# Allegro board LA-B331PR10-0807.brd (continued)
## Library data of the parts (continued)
U5 U51 U54 U60 U61 UH1 = SN74AHC1G08DCKR_SC70-5
U6 = APL3512ABI-TRG_SOT23-5
U7 = SN74AHC1G04DCKR_SOT23-5
U21 = AT97SC3205_TSSOP28
U24 U34 U57 U59 = APE8937GN2_DFN8_2X2
U25-U27 U29 U30 U33 = TPS22966DPUR_SON14_2X3
U28 = NCP4545IMNTWG_QFN18_3X3
U37 UC1 = 74AUP1G07GW_TSSOP5
U38 = MEC1641-PZV_TFBGA_144P
U46 = APX9136QFI-TRG_VTDFN6_1P6X1P6
U53 = TXB0104YZTR_DSBGA_12P
U56 = PS8713BTQFN24GTR2_TQFN24_4X4
U58 = G601A31U_ADFN6_1P5X1P5
UCPU1 = BDW-Y-LPDDR3_BGA_1234P-T
UD1-UD8 = MT41J256M16RE-15E-D_FBGA_96P
Y3 = Y_9H03200031_2P
YH1 = Y_9H03220008_2P
YH2 = Y_X3G024000DC1H_4P

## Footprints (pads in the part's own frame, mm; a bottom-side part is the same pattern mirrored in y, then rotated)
74AUP1G07GW_TSSOP5
  oval 0.381x1.346 smd: 1(0,0) 2(0.65,0) 3(1.3,0) 4(1.3,1.79) 5(0,1.79)
74CBTLV3126DS_SSOP16
  oval 0.381x1.676 smd: 1(0,0) 2(0.635,0) 3(1.27,0) 4(1.905,0) 5(2.54,0) 6(3.175,0) 7(3.81,0) 8(4.445,0) 9(4.445,5.35) 10(3.81,5.35) 11(3.175,5.35) 12(2.54,5.35) 13(1.905,5.35) 14(1.27,5.35) 15(0.635,5.35) 16(0,5.35)
ACES_50278-00201-001_2P
  oval 0.787x1.905 smd: 1(0,0) 2(1.25,0)
  rect 1.295x3.353 smd: 3(-2.85,-4.925) 4(4.1,-4.925)
ACES_50281-00601-001_6P-T
  oval 0.787x2.007 smd: 1(0,0) 2(1.25,0) 3(2.5,0) 4(3.75,0) 5(5,0) 6(6.25,0)
  rect 2.007x2.489 smd: 7(-2.2,-4.05) 8(8.45,-4.05)
ACES_50406-02071-001_20P
  oval 0.254x1.295 smd: 1(0,0) 2(0.5,0) 3(1,0) 4(1.5,0) 5(2,0) 6(2.5,0) 7(3,0) 8(3.5,0) 9(4,0) 10(4.5,0) 11(5,0) 12(5.5,0) 13(6,0) 14(6.5,0) 15(7,0) 16(7.5,0) 17(8,0) 18(8.5,0) 19(9,0) 20(9.5,0)
  rect 1.194x2.692 smd: 21(-2.4,1.95) 22(11.9,1.95)
  rect 2.311x1.295 smd: 23(0.85,3.9) 24(8.65,3.9)
ACES_50406-03071-001_30P
  oval 0.254x1.295 smd: 1(0,0) 2(0.5,0) 3(1,0) 4(1.5,0) 5(2,0) 6(2.5,0) 7(3,0) 8(3.5,0) 9(4,0) 10(4.5,0) 11(5,0) 12(5.5,0) 13(6,0) 14(6.5,0) 15(7,0) 16(7.5,0) 17(8,0) 18(8.5,0) 19(9,0) 20(9.5,0) 21(10,0) 22(10.5,0) 23(11,0) 24(11.5,0) 25(12,0) 26(12.5,0) 27(13,0) 28(13.5,0) 29(14,0) 30(14.5,0)
  rect 1.194x2.692 smd: 31(16.9,1.95) 35(-2.4,1.95)
  rect 2.311x1.295 smd: 32(13.65,3.9) 33(7.25,3.9) 34(0.85,3.9)
ACES_50521-0084N-P01_8P
  oval 0.305x1.092 smd: 1(0,0) 2(-0.5,0) 3(-1,0) 4(-1.5,0) 5(-2,0) 6(-2.5,0) 7(-3,0) 8(-3.5,0)
  rect 0.406x0.787 smd: 9(1,-2.65) 10(-4.5,-2.65)
ACES_50521-01041-P01_10P
  oval 0.305x0.787 smd: 1(0,0) 2(0.5,0) 3(1,0) 4(1.5,0) 5(2,0) 6(2.5,0) 7(3,0) 8(3.5,0) 9(4,0) 10(4.5,0)
  rect 0.406x0.787 smd: 11(-1,-2.5) 12(5.5,-2.5)
ACES_50696-0200M-001_20P-T
  oval 0.305x0.787 smd: 1(0,0) 2(0.5,0) 3(1,0) 4(1.5,0) 5(2,0) 6(2.5,0) 7(3,0) 8(3.5,0) 9(4,0) 10(4.5,0) 11(5,0) 12(5.5,0) 13(6,0) 14(6.5,0) 15(7,0) 16(7.5,0) 17(8,0) 18(8.5,0) 19(9,0) 20(9.5,0)
  rect 0.406x0.787 smd: 21(-1,-2.5) 22(10.5,-2.5)
ACES_51015-05001-002_50P
  oval 0.203x0.762 smd: 1(0,0) 2(0,3.95) 3(0.4,0) 4(0.4,3.95) 5(0.8,0) 6(0.8,3.95) 7(1.2,0) 8(1.2,3.95) 9(1.6,0) 10(1.6,3.95) 11(2,0) 12(2,3.95) 13(2.4,0) 14(2.4,3.95) 15(2.8,0) 16(2.8,3.95) 17(3.2,0) 18(3.2,3.95) 19(3.6,0) 20(3.6,3.95) 21(4,0) 22(4,3.95) 23(4.4,0) 24(4.4,3.95) 25(4.8,0) 26(4.8,3.95) 27(5.2,0) 28(5.2,3.95) 29(5.6,0) 30(5.6,3.95) 31(6,0) 32(6,3.95) 33(6.4,0) 34(6.4,3.95) 35(6.8,0) 36(6.8,3.95) 37(7.2,0) 38(7.2,3.95) 39(7.6,0) 40(7.6,3.95) 41(8,0) 42(8,3.95) 43(8.4,0) 44(8.4,3.95) 45(8.8,0) 46(8.8,3.95) 47(9.2,0) 48(9.2,3.95) 49(9.6,0) 50(9.6,3.95)
  rect 0.559x0.508 smd: 51(-1.115,2.425) 52(-1.115,1.525) 53(10.715,2.425) 54(10.715,1.525)
AON7405_DFN8-5
  oval 0.406x0.991 smd: 1(0,0) 2(0.66,0) 3(1.32,0) 4(1.98,0)
  custom 0.559x0.559 smd: 5(0.99,2.247)
AON7934_DFN3X3A8-10
  oval 0.457x0.508 smd: 1(0,0) 2(0.65,0) 3(1.3,0) 4(1.95,0) 5(1.95,2.76) 6(1.3,2.76) 7(0.65,2.76) 8(0,2.76)
  rect 2.54x1.041 smd: 9(0.975,1.813)
  rect 2.54x0.559 smd: 10(0.975,0.708)
APE8937GN2_DFN8_2X2
  oval 0.254x0.787 smd: 1(0,0) 2(0.5,0) 3(1,0) 4(1.5,0) 5(1.5,2.2) 6(1,2.2) 7(0.5,2.2) 8(0,2.2)
  rect 1.6x0.889 smd: 9(0.75,1.1)
APL3512ABI-TRG_SOT23-5
  oval 0.61x1.041 smd: 1(0,0) 2(0.95,0) 3(1.9,0) 4(1.9,2.7) 5(0,2.7)
APX9136QFI-TRG_VTDFN6_1P6X1P6
  oval 0.254x0.737 smd: 1(0,0) 2(0.5,0) 3(1,0) 4(1,1.86) 5(0.5,1.86) 6(0,1.86)
  rect 0.991x0.61 smd: 7(0.5,0.93)
AT97SC3205_TSSOP28
  oval 0.381x1.626 smd: 1(0,0) 2(0.65,0) 3(1.3,0) 4(1.95,0) 5(2.6,0) 6(3.25,0) 7(3.9,0) 8(4.55,0) 9(5.2,0) 10(5.85,0) 11(6.5,0) 12(7.15,0) 13(7.8,0) 14(8.45,0) 15(8.45,5.8) 16(7.8,5.8) 17(7.15,5.8) 18(6.5,5.8) 19(5.85,5.8) 20(5.2,5.8) 21(4.55,5.8) 22(3.9,5.8) 23(3.25,5.8) 24(2.6,5.8) 25(1.95,5.8) 26(1.3,5.8) 27(0.65,5.8) 28(0,5.8)
BAT54CW-7-F_SOT323-3
  oval 0.711x0.889 smd: 1(0,0) 2(-0.65,-1.9) 3(0.65,-1.9)
BAT54CW_SOT323-3
  oval 0.61x0.559 smd: 1(0,0) 2(-0.65,-1.85) 3(0.65,-1.85)
BAT54HT1G_SOD323-2
  rect 0.635x0.838 smd: 1(0,0) 2(2.225,0)
BDW-Y-LPDDR3_BGA_1234P-T
  round 0.305 smd: A6(-1.25,0) A42(-14.484,0) A44(-14.984,0) C5(-1,0.433) C43(-14.734,0.433) C45(-15.234,0.433) CR45(-15.234,27.435) CU1(0,27.984) CU44(-14.984,27.868) CV3(-0.435,28.234) CV43(-14.734,28.301) CV45(-15.234,28.301) CW1(0,28.484) CW5(-0.868,28.484) CY3(-0.435,28.734) CY7(-1.301,28.734) CY42(-14.484,28.734) CY44(-14.984,28.734) D2(-0.25,0.866) D4(-0.75,0.866) D44(-14.984,0.866) F1(0,1.299) F3(-0.5,1.299) F45(-15.234,1.299) H2(-0.25,1.732) J1(0,2.165)
  round 0.279 smd: A8(-1.75,0) A10(-2.25,0) A14(-3.3,0) A16(-4.166,0) A18(-5.032,0) A20(-5.898,0) A22(-6.764,0) A24(-7.63,0) A26(-8.496,0) A28(-9.362,0) A30(-10.228,0) A32(-11.094,0) A34(-11.96,0) A36(-12.943,0) A38(-13.484,0) A40(-13.984,0) AA1(0,5.629) AA45(-15.234,5.629) AC1(0,6.495) AC45(-15.234,6.495) AE1(0,7.361) AE45(-15.234,7.361) AG1(0,8.227) AG45(-15.234,8.227) AJ1(0,9.093) AJ45(-15.234,9.093) AM1(0,9.959) AM45(-15.234,9.959) AP1(0,10.903) AP45(-15.234,10.903) AT1(0,11.769) AT45(-15.234,11.769) AV1(0,12.635) AV45(-15.234,12.635) AY1(0,13.501) AY45(-15.234,13.501) BB1(0,14.367) BB45(-15.234,14.367) BD1(0,15.233) BD45(-15.234,15.233) BF1(0,16.099) BF45(-15.234,16.099) BH1(0,16.965) BH45(-15.234,16.965) BK1(0,17.831) BK45(-15.234,17.831) BM1(0,18.697) BM45(-15.234,18.697) BP1(0,19.563) BP45(-15.234,19.563) BT1(0,20.429) BT45(-15.234,20.429) BV1(0,21.295) BV45(-15.234,21.295) BY1(0,22.161) BY45(-15.234,22.161) CB1(0,23.027) CB45(-15.234,23.027) CD1(0,23.893) CD45(-15.234,23.893) CF1(0,24.759) CF45(-15.234,24.759) CH1(0,25.703) CH45(-15.234,25.703) CL1(0,26.484) CM45(-15.234,26.569) CN1(0,26.984) CR1(0,27.484) CY10(-2.167,28.734) CY13(-3.033,28.734) CY15(-3.899,28.734) CY17(-4.765,28.734) CY19(-5.631,28.734) CY21(-6.497,28.734) CY23(-7.363,28.734) CY25(-8.229,28.734) CY27(-9.095,28.734) CY29(-9.961,28.734) CY31(-10.827,28.734) CY33(-11.693,28.734) CY36(-12.984,28.734) CY38(-13.484,28.734) CY40(-13.984,28.734) J45(-15.234,2.165) N1(0,3.031) N45(-15.234,3.031) T1(0,3.897) T45(-15.234,3.897) W1(0,4.763) W45(-15.234,4.763)
  round 0.254 smd: AA3(-0.5,5.629) AA5(-1,5.629) AA7(-1.5,5.629) AA9(-2,5.629) AA11(-2.5,5.629) AA13(-3,5.629) AA15(-3.5,5.629) AA17(-4.552,5.549) AA18(-5.107,5.707) AA19(-5.707,5.707) AA21(-6.307,5.707) AA22(-6.859,5.707) AA24(-7.459,5.707) AA25(-8.059,5.707) AA26(-8.611,5.707) AA28(-9.211,5.707) AA29(-9.811,5.707) AA30(-10.363,5.707) AA32(-10.963,5.707) AA33(-11.563,5.707) AA34(-12.115,5.707) AA35(-12.734,5.629) AA37(-13.234,5.629) AA39(-13.734,5.629) AA41(-14.234,5.629) AA43(-14.734,5.629) AB2(-0.25,6.062) AB4(-0.75,6.062) AB6(-1.25,6.062) AB8(-1.75,6.062) AB10(-2.25,6.062) AB12(-2.75,6.062) AB14(-3.25,6.062) AB15(-4.057,6.249) AB16(-4.087,5.749) AB36(-12.984,6.062) AB38(-13.484,6.062) AB40(-13.984,6.062) AB42(-14.484,6.062) AB44(-14.984,6.062) AC3(-0.5,6.495) AC5(-1,6.495) AC7(-1.5,6.495) AC9(-2,6.495) AC11(-2.5,6.495) AC13(-3,6.495) AC15(-3.5,6.495) AC17(-4.555,6.316) AC18(-5.107,6.316) AC19(-5.707,6.316) AC21(-6.307,6.316) AC22(-6.859,6.316) AC24(-7.459,6.316) AC25(-8.059,6.316) AC26(-8.611,6.316) AC28(-9.211,6.316) AC29(-9.811,6.316) AC30(-10.363,6.316) AC32(-10.963,6.316) AC33(-11.563,6.316) AC34(-12.115,6.316) AC35(-12.734,6.495) AC37(-13.234,6.495) AC39(-13.734,6.495) AC41(-14.234,6.495) AC43(-14.734,6.495) AD2(-0.25,6.928) AD4(-0.75,6.928) AD6(-1.25,6.928) AD8(-1.75,6.928) AD10(-2.25,6.928) AD12(-2.75,6.928) AD14(-3.25,6.928) AD16(-4.067,6.77) AD17(-4.555,6.924) AD18(-5.107,6.924) AD19(-5.707,6.924) AD21(-6.307,6.924) AD22(-6.859,6.924) AD24(-7.459,6.924) AD25(-8.059,6.924) AD26(-8.611,6.924) AD28(-9.211,6.924) AD29(-9.811,6.924) AD30(-10.363,6.924) AD32(-10.963,6.924) AD33(-11.563,6.924) AD34(-12.115,6.924) AD36(-12.984,6.928) AD38(-13.484,6.928) AD40(-13.984,6.928) AD42(-14.484,6.928) AD44(-14.984,6.928) AE3(-0.5,7.361) AE5(-1,7.361) AE7(-1.5,7.361) AE9(-2,7.361) AE11(-2.5,7.361) AE13(-3,7.361) AE15(-3.5,7.361) AE16(-4.117,7.286) AE17(-4.555,7.533) AE18(-5.107,7.533) AE19(-5.707,7.533) AE21(-6.307,7.533) AE22(-6.859,7.533) AE24(-7.459,7.533) AE25(-8.059,7.533) AE26(-8.611,7.533) AE28(-9.211,7.533) AE29(-9.811,7.533) AE30(-10.363,7.533) AE32(-10.963,7.533) AE33(-11.563,7.533) AE34(-12.115,7.533) AE35(-12.734,7.361) AE37(-13.234,7.361) AE39(-13.734,7.361) AE41(-14.234,7.361) AE43(-14.734,7.361) AF2(-0.25,7.794) AF4(-0.75,7.794) AF6(-1.25,7.794) AF8(-1.75,7.794) AF10(-2.25,7.794) AF12(-2.75,7.794) AF14(-3.25,7.794) AF16(-4.097,7.94) AF36(-12.984,7.794) AF38(-13.484,7.794) AF40(-13.984,7.794) AF42(-14.484,7.794) AF44(-14.984,7.794) AG3(-0.5,8.227) AG5(-1,8.227) AG7(-1.5,8.227) AG9(-2,8.227) AG11(-2.5,8.227) AG13(-3,8.227) AG14(-3.5,8.227) AG16(-4.555,8.141) AG18(-5.107,8.141) AG19(-5.707,8.141) AG21(-6.307,8.141) AG22(-6.859,8.141) AG24(-7.459,8.141) AG25(-8.059,8.141) AG26(-8.611,8.141) AG28(-9.211,8.141) AG29(-9.811,8.141) AG30(-10.363,8.141) AG32(-10.963,8.141) AG33(-11.563,8.141) AG34(-12.115,8.141) AG35(-12.734,8.227) AG37(-13.234,8.227) AG39(-13.734,8.227) AG41(-14.234,8.227) AG43(-14.734,8.227) AH2(-0.25,8.66) AH4(-0.75,8.66) AH6(-1.25,8.66) AH8(-1.75,8.66) AH10(-2.25,8.66) AH12(-2.75,8.66) AH14(-3.25,8.66) AH15(-3.75,8.66) AH16(-4.367,8.66) AH17(-4.867,8.66) AH19(-5.367,8.66) AH20(-5.867,8.66) AH21(-6.367,8.66) AH22(-6.867,8.66) AH23(-7.367,8.66) AH25(-7.867,8.66) AH26(-8.367,8.66) AH27(-8.867,8.66) AH28(-9.367,8.66) AH29(-9.867,8.66) AH30(-10.367,8.66) AH31(-10.867,8.66) AH32(-11.367,8.66) AH33(-11.867,8.66) AH34(-12.367,8.66) AH36(-12.984,8.66) AH38(-13.484,8.66) AH40(-13.984,8.66) AH42(-14.484,8.66) AH44(-14.984,8.66) AJ3(-0.5,9.093) AJ5(-1,9.093) AJ7(-1.5,9.093) AJ9(-2,9.093) AJ11(-2.5,9.093) AJ13(-3,9.093) AJ14(-3.526,9.212) AJ16(-4.446,9.161) AJ18(-5.312,9.161) AJ20(-6.178,9.161) AJ22(-7.044,9.161) AJ24(-7.91,9.161) AJ26(-8.776,9.161) AJ28(-9.642,9.161) AJ30(-10.508,9.161) AJ32(-11.374,9.161) AJ34(-12.24,9.161) AJ37(-13.234,9.093) AJ39(-13.734,9.093) AJ41(-14.234,9.093) AJ43(-14.734,9.093) AK2(-0.25,9.526) AK4(-0.75,9.526) AK6(-1.25,9.526) AK8(-1.75,9.526) AK10(-2.25,9.526) AK12(-2.75,9.526) AK15(-3.993,9.391) AK17(-4.879,9.411) AK19(-5.745,9.411) AK21(-6.611,9.411) AK23(-7.477,9.411) AK25(-8.343,9.411) AK27(-9.209,9.411) AK29(-10.075,9.411) AK31(-10.941,9.411) AK33(-11.807,9.411) AK35(-12.673,9.411) AK42(-14.484,9.526) AK44(-14.984,9.526) AL14(-3.583,9.807) AL16(-4.446,9.661) AL18(-5.312,9.661) AL20(-6.178,9.661) AL22(-7.044,9.661) AL24(-7.91,9.661) AL26(-8.776,9.661) AL28(-9.642,9.661) AL30(-10.508,9.661) AL32(-11.374,9.661) AL34(-12.24,9.661) AL37(-13.214,9.659) AL39(-13.814,9.659) AM3(-0.5,9.959) AM5(-1,9.959) AM7(-1.5,9.959) AM9(-2,9.959) AM11(-2.5,9.959) AM13(-3,9.959) AM17(-4.879,9.911) AM19(-5.745,9.911) AM21(-6.611,9.911) AM23(-7.477,9.911) AM25(-8.343,9.911) AM27(-9.209,9.911) AM29(-10.075,9.911) AM31(-10.941,9.911) AM33(-11.807,9.911) AM35(-12.673,9.911) AM39(-13.403,10.303) AM41(-14.234,9.959) AM43(-14.734,9.959) AN2(-0.25,10.47) AN4(-0.75,10.47) AN6(-1.25,10.47) AN8(-1.75,10.47) AN10(-2.25,10.47) AN12(-2.75,10.47) AN14(-3.416,10.47) AN40(-13.984,10.47) AN42(-14.484,10.47) AN44(-14.984,10.47) AP3(-0.5,10.903) AP5(-1,10.903) AP7(-1.5,10.903) AP9(-2,10.903) AP11(-2.5,10.903) AP13(-3,10.903) AP15(-3.831,10.903) AP39(-13.403,10.903) AP41(-14.234,10.903) AP43(-14.734,10.903) AR2(-0.25,11.336) AR4(-0.75,11.336) AR6(-1.25,11.336) AR8(-1.75,11.336) AR10(-2.25,11.336) AR12(-2.75,11.336) AR14(-3.416,11.336) AR40(-13.819,11.336) AR42(-14.484,11.336) AR44(-14.984,11.336) AT3(-0.5,11.769) AT5(-1,11.769) AT7(-1.5,11.769) AT9(-2,11.769) AT11(-2.5,11.769) AT13(-3,11.769) AT15(-3.831,11.769) AT39(-13.403,11.769) AT41(-14.234,11.769) AT43(-14.734,11.769) AU2(-0.25,12.202) AU4(-0.75,12.202) AU6(-1.25,12.202) AU8(-1.75,12.202) AU10(-2.25,12.202) AU12(-2.75,12.202) AU14(-3.416,12.202) AU40(-13.819,12.202) AU42(-14.484,12.202) AU44(-14.984,12.202) AV3(-0.5,12.635) AV5(-1,12.635) AV7(-1.5,12.635) AV9(-2,12.635) AV11(-2.5,12.635) AV13(-3,12.635) AV15(-3.831,12.635) AV39(-13.403,12.635) AV41(-14.234,12.635) AV43(-14.734,12.635) AW2(-0.25,13.068) AW4(-0.75,13.068) AW6(-1.25,13.068) AW8(-1.75,13.068) AW10(-2.25,13.068) AW12(-2.75,13.068) AW14(-3.416,13.068) AW40(-13.819,13.068) AW42(-14.484,13.068) AW44(-14.984,13.068) AY3(-0.5,13.501) AY5(-1,13.501) AY7(-1.5,13.501) AY9(-2,13.501) AY11(-2.5,13.501) AY13(-3,13.501) AY15(-3.831,13.501) AY39(-13.403,13.501) AY41(-14.234,13.501) AY43(-14.734,13.501) B13(-2.867,0.25) B15(-3.733,0.25) B17(-4.599,0.25) B19(-5.465,0.25) B21(-6.331,0.25) B23(-7.197,0.25) B25(-8.063,0.25) B27(-8.929,0.25) B29(-9.795,0.25) B31(-10.661,0.25) B33(-11.527,0.25) B35(-12.393,0.25) BA2(-0.25,13.934) BA4(-0.75,13.934) BA6(-1.25,13.934) BA8(-1.75,13.934) BA10(-2.25,13.934) BA12(-2.75,13.934) BA14(-3.416,13.934) BA40(-13.819,13.934) BA42(-14.484,13.934) BA44(-14.984,13.934) BB3(-0.5,14.367) BB5(-1,14.367) BB7(-1.5,14.367) BB9(-2,14.367) BB11(-2.5,14.367) BB13(-3,14.367) BB15(-3.831,14.367) BB39(-13.403,14.367) BB41(-14.234,14.367) BB43(-14.734,14.367) BC2(-0.25,14.8) BC4(-0.75,14.8) BC6(-1.25,14.8) BC8(-1.75,14.8) BC10(-2.25,14.8) BC12(-2.75,14.8) BC14(-3.416,14.8) BC40(-13.819,14.8) BC42(-14.484,14.8) BC44(-14.984,14.8) BD3(-0.5,15.233) BD5(-1,15.233) BD7(-1.5,15.233) BD9(-2,15.233) BD11(-2.5,15.233) BD13(-3,15.233) BD15(-3.831,15.233) BD39(-13.403,15.233) BD41(-14.234,15.233) BD43(-14.734,15.233) BE2(-0.25,15.666) BE4(-0.75,15.666) BE6(-1.25,15.666) BE8(-1.75,15.666) BE10(-2.25,15.666) BE12(-2.75,15.666) BE14(-3.416,15.666) BE40(-13.819,15.666) BE42(-14.484,15.666) BE44(-14.984,15.666) BF3(-0.5,16.099) BF5(-1,16.099) BF7(-1.5,16.099) BF9(-2,16.099) BF11(-2.5,16.099) BF13(-3,16.099) BF15(-3.831,16.099) BF39(-13.403,16.099) BF41(-14.234,16.099) BF43(-14.734,16.099) BG2(-0.25,16.532) BG4(-0.75,16.532) BG6(-1.25,16.532) BG8(-1.75,16.532) BG10(-2.25,16.532) BG12(-2.75,16.532) BG14(-3.416,16.532) BG40(-13.819,16.532) BG42(-14.484,16.532) BG44(-14.984,16.532) BH3(-0.5,16.965) BH5(-1,16.965) BH7(-1.5,16.965) BH9(-2,16.965) BH11(-2.5,16.965) BH13(-3,16.965) BH15(-3.831,16.965) BH39(-13.403,16.965) BH41(-14.234,16.965) BH43(-14.734,16.965) BJ2(-0.25,17.398) BJ4(-0.75,17.398) BJ6(-1.25,17.398) BJ8(-1.75,17.398) BJ10(-2.25,17.398) BJ12(-2.75,17.398) BJ14(-3.416,17.398) BJ40(-13.819,17.398) BJ42(-14.484,17.398) BJ44(-14.984,17.398) BK3(-0.5,17.831) BK5(-1,17.831) BK7(-1.5,17.831) BK9(-2,17.831) BK11(-2.5,17.831) BK13(-3,17.831) BK15(-3.831,17.831) BK39(-13.403,17.831) BK41(-14.234,17.831) BK43(-14.734,17.831) BL2(-0.25,18.264) BL4(-0.75,18.264) BL6(-1.25,18.264) BL8(-1.75,18.264) BL10(-2.25,18.264) BL12(-2.75,18.264) BL14(-3.416,18.264) BL40(-13.819,18.264) BL42(-14.484,18.264) BL44(-14.984,18.264) BM3(-0.5,18.697) BM5(-1,18.697) BM7(-1.5,18.697) BM9(-2,18.697) BM11(-2.5,18.697) BM13(-3,18.697) BM15(-3.831,18.697) BM39(-13.403,18.697) BM41(-14.234,18.697) BM43(-14.734,18.697) BN2(-0.25,19.13) BN4(-0.75,19.13) BN6(-1.25,19.13) BN8(-1.75,19.13) BN10(-2.25,19.13) BN12(-2.75,19.13) BN14(-3.416,19.13) BN40(-13.819,19.13) BN42(-14.484,19.13) BN44(-14.984,19.13) BP3(-0.5,19.563) BP5(-1,19.563) BP7(-1.5,19.563) BP9(-2,19.563) BP11(-2.5,19.563) BP13(-3,19.563) BP15(-3.831,19.563) BP39(-13.403,19.563) BP41(-14.234,19.563) BP43(-14.734,19.563) BR2(-0.25,19.996) BR4(-0.75,19.996) BR6(-1.25,19.996) BR8(-1.75,19.996) BR10(-2.25,19.996) BR12(-2.75,19.996) BR14(-3.416,19.996) BR40(-13.819,19.996) BR42(-14.484,19.996) BR44(-14.984,19.996) BT3(-0.5,20.429) BT5(-1,20.429) BT7(-1.5,20.429) BT9(-2,20.429) BT11(-2.5,20.429) BT13(-3,20.429) BT15(-3.831,20.429) BT39(-13.403,20.429) BT41(-14.234,20.429) BT43(-14.734,20.429) BU2(-0.25,20.862) BU4(-0.75,20.862) BU6(-1.25,20.862) BU8(-1.75,20.862) BU10(-2.25,20.862) BU12(-2.75,20.862) BU14(-3.416,20.862) BU40(-13.819,20.862) BU42(-14.484,20.862) BU44(-14.984,20.862) BV3(-0.5,21.295) BV5(-1,21.295) BV7(-1.5,21.295) BV9(-2,21.295) BV11(-2.5,21.295) BV13(-3,21.295) BV15(-3.831,21.295) BV39(-13.403,21.295) BV41(-14.234,21.295) BV43(-14.734,21.295) BW2(-0.25,21.728) BW4(-0.75,21.728) BW6(-1.25,21.728) BW8(-1.75,21.728) BW10(-2.25,21.728) BW12(-2.75,21.728) BW14(-3.416,21.728) BW40(-13.819,21.728) BW42(-14.484,21.728) BW44(-14.984,21.728) BY3(-0.5,22.161) BY5(-1,22.161) BY7(-1.5,22.161) BY9(-2,22.161) BY11(-2.5,22.161) BY13(-3,22.161) BY15(-3.831,22.161) BY39(-13.403,22.161) BY41(-14.234,22.161) BY43(-14.734,22.161) C7(-1.5,0.433) C9(-2,0.433) C14(-3.3,0.5) C16(-4.166,0.5) C18(-5.032,0.5) C20(-5.898,0.5) C22(-6.764,0.5) C24(-7.63,0.5) C26(-8.496,0.5) C28(-9.362,0.5) C30(-10.228,0.5) C32(-11.094,0.5) C34(-11.96,0.5) C36(-13.154,0.489) C39(-13.734,0.433) C41(-14.234,0.433) CA2(-0.25,22.594) CA4(-0.75,22.594) CA6(-1.25,22.594) CA8(-1.75,22.594) CA10(-2.25,22.594) CA12(-2.75,22.594) CA14(-3.416,22.594) CA40(-13.819,22.594) CA42(-14.484,22.594) CA44(-14.984,22.594) CB3(-0.5,23.027) CB5(-1,23.027) CB7(-1.5,23.027) CB9(-2,23.027) CB11(-2.5,23.027) CB13(-3,23.027) CB15(-3.831,23.027) CB39(-13.403,23.027) CB41(-14.234,23.027) CB43(-14.734,23.027) CC2(-0.25,23.46) CC4(-0.75,23.46) CC6(-1.25,23.46) CC8(-1.75,23.46) CC10(-2.25,23.46) CC12(-2.75,23.46) CC14(-3.416,23.46) CC40(-13.819,23.46) CC42(-14.484,23.46) CC44(-14.984,23.46) CD3(-0.5,23.893) CD5(-1,23.893) CD7(-1.5,23.893) CD9(-2,23.893) CD11(-2.5,23.893) CD13(-3,23.893) CD15(-3.831,23.893) CD39(-13.403,23.893) CD41(-14.234,23.893) CD43(-14.734,23.893) CE2(-0.25,24.326) CE4(-0.75,24.326) CE6(-1.25,24.326) CE8(-1.75,24.326) CE10(-2.25,24.326) CE12(-2.75,24.326) CE14(-3.416,24.326) CE40(-13.819,24.326) CE42(-14.484,24.326) CE44(-14.984,24.326) CF3(-0.5,24.759) CF5(-1,24.759) CF7(-1.5,24.759) CF9(-2,24.759) CF11(-2.5,24.759) CF13(-3,24.759) CF15(-3.831,24.759) CF39(-13.403,24.759) CF41(-14.234,24.759) CF43(-14.734,24.759) CG2(-0.25,25.192) CG4(-0.75,25.192) CG6(-1.25,25.192) CG8(-1.75,25.192) CG10(-2.25,25.192) CG12(-2.75,25.192) CG14(-3.416,25.192) CG40(-13.819,25.192) CG42(-14.484,25.192) CG44(-14.984,25.192) CH3(-0.5,25.703) CH5(-1,25.703) CH7(-1.5,25.703) CH9(-2,25.703) CH11(-2.5,25.703) CH13(-3,25.703) CH15(-3.567,25.747) CH39(-13.403,25.625) CH41(-14.234,25.703) CH43(-14.734,25.703) CJ16(-4.332,25.984) CJ18(-5.198,25.984) CJ20(-6.064,25.984) CJ22(-6.93,25.984) CJ24(-7.796,25.984) CJ26(-8.662,25.984) CJ28(-9.528,25.984) CJ30(-10.394,25.984) CJ32(-11.26,25.984) CJ34(-12.126,25.984) CK3(-0.437,26.227) CK6(-1.25,26.136) CK10(-2.187,26.197) CK13(-3.047,26.207) CK15(-3.877,26.197) CK17(-4.765,26.234) CK19(-5.631,26.234) CK21(-6.497,26.234) CK23(-7.363,26.234) CK25(-8.229,26.234) CK27(-9.095,26.234) CK29(-9.961,26.234) CK31(-10.827,26.234) CK33(-11.693,26.234) CK36(-12.984,26.136) CK38(-13.484,26.136) CK40(-13.984,26.136) CK42(-14.484,26.136) CK44(-14.984,26.136) CL5(-0.868,26.484) CL8(-1.734,26.484) CL12(-2.6,26.484) CL14(-3.466,26.484) CL16(-4.332,26.484) CL18(-5.198,26.484) CL20(-6.064,26.484) CL22(-6.93,26.484) CL24(-7.796,26.484) CL26(-8.662,26.484) CL28(-9.528,26.484) CL30(-10.394,26.484) CL32(-11.26,26.484) CL34(-12.126,26.484) CM3(-0.435,26.734) CM7(-1.301,26.734) CM10(-2.167,26.734) CM13(-3.033,26.734) CM15(-3.899,26.734) CM17(-4.765,26.734) CM19(-5.631,26.734) CM21(-6.497,26.734) CM23(-7.363,26.734) CM25(-8.229,26.734) CM27(-9.095,26.734) CM29(-9.961,26.734) CM31(-10.827,26.734) CM33(-11.693,26.734) CM35(-12.734,26.569) CM37(-13.234,26.569) CM39(-13.734,26.569) CM41(-14.234,26.569) CM43(-14.734,26.569) CN5(-0.868,26.984) CN8(-1.734,26.984) CN12(-2.6,26.984) CN14(-3.466,26.984) CN16(-4.332,26.984) CN18(-5.198,26.984) CN20(-6.064,26.984) CN22(-6.93,26.984) CN24(-7.796,26.984) CN26(-8.662,26.984) CN28(-9.528,26.984) CN30(-10.394,26.984) CN32(-11.26,26.984) CN34(-12.126,26.984) CN36(-12.984,27.002) CN38(-13.484,27.002) CN40(-13.984,27.002) CN42(-14.484,27.002) CN44(-14.984,27.002) CP3(-0.435,27.234) CP7(-1.301,27.234) CP10(-2.167,27.234) CP13(-3.033,27.234) CP15(-3.899,27.234) CP17(-4.765,27.234) CP19(-5.631,27.234) CP21(-6.497,27.234) CP23(-7.363,27.234) CP25(-8.229,27.234) CP27(-9.095,27.234) CP29(-9.961,27.234) CP31(-10.827,27.234) CP33(-11.693,27.234) CR5(-0.868,27.484) CR8(-1.734,27.484) CR12(-2.6,27.484) CR14(-3.466,27.484) CR16(-4.332,27.484) CR18(-5.198,27.484) CR20(-6.064,27.484) CR22(-6.93,27.484) CR24(-7.796,27.484) CR26(-8.662,27.484) CR28(-9.528,27.484) CR30(-10.394,27.484) CR32(-11.26,27.484) CR34(-12.126,27.484) CR35(-12.734,27.435) CR37(-13.234,27.435) CR39(-13.734,27.435) CR41(-14.234,27.435) CR43(-14.734,27.435) CT3(-0.435,27.734) CT7(-1.301,27.734) CT10(-2.167,27.734) CT13(-3.033,27.734) CT15(-3.899,27.734) CT17(-4.765,27.734) CT19(-5.631,27.734) CT21(-6.497,27.734) CT23(-7.363,27.734) CT25(-8.229,27.734) CT27(-9.095,27.734) CT29(-9.961,27.734) CT31(-10.827,27.734) CT33(-11.693,27.734) CU5(-0.868,27.984) CU8(-1.734,27.984) CU12(-2.6,27.984) CU14(-3.466,27.984) CU16(-4.332,27.984) CU18(-5.198,27.984) CU20(-6.064,27.984) CU22(-6.93,27.984) CU24(-7.796,27.984) CU26(-8.662,27.984) CU28(-9.528,27.984) CU30(-10.394,27.984) CU32(-11.26,27.984) CU34(-12.126,27.984) CU36(-12.984,27.868) CU38(-13.484,27.868) CU40(-13.984,27.868) CU42(-14.484,27.868) CV7(-1.301,28.234) CV10(-2.167,28.234) CV13(-3.033,28.234) CV15(-3.899,28.234) CV17(-4.765,28.234) CV19(-5.631,28.234) CV21(-6.497,28.234) CV23(-7.363,28.234) CV25(-8.229,28.234) CV27(-9.095,28.234) CV29(-9.961,28.234) CV31(-10.827,28.234) CV33(-11.693,28.234) CV35(-12.734,28.301) CV37(-13.234,28.301) CV39(-13.734,28.301) CV41(-14.234,28.301) CW8(-1.734,28.484) CW12(-2.6,28.484) CW14(-3.466,28.484) CW16(-4.332,28.484) CW18(-5.198,28.484) CW20(-6.064,28.484) CW22(-6.93,28.484) CW24(-7.796,28.484) CW26(-8.662,28.484) CW28(-9.528,28.484) CW30(-10.394,28.484) CW32(-11.26,28.484) CW34(-12.126,28.484) D6(-1.25,0.866) D8(-1.75,0.866) D10(-2.25,0.866) D13(-2.867,0.75) D15(-3.733,0.75) D17(-4.599,0.75) D19(-5.465,0.75) D21(-6.331,0.75) D23(-7.197,0.75) D25(-8.063,0.75) D27(-8.929,0.75) D29(-9.795,0.75) D31(-10.661,0.75) D33(-11.527,0.75) D35(-12.393,0.75) D38(-13.484,0.866) D40(-13.984,0.866) D42(-14.484,0.866) E14(-3.3,1) E16(-4.166,1) E18(-5.032,1) E20(-5.898,1) E22(-6.764,1) E24(-7.63,1) E26(-8.496,1) E28(-9.362,1) E30(-10.228,1) E32(-11.094,1) E34(-11.96,1) E36(-12.843,0.98) F5(-1,1.299) F7(-1.5,1.299) F9(-2,1.299) F13(-2.867,1.25) F15(-3.733,1.25) F17(-4.599,1.25) F19(-5.465,1.25) F21(-6.331,1.25) F23(-7.197,1.25) F25(-8.063,1.25) F27(-8.929,1.25) F29(-9.795,1.25) F31(-10.661,1.25) F33(-11.527,1.25) F35(-12.393,1.25) F37(-13.234,1.299) F39(-13.734,1.299) F41(-14.234,1.299) F43(-14.734,1.299) G14(-3.3,1.5) G16(-4.166,1.5) G18(-5.032,1.5) G20(-5.898,1.5) G22(-6.764,1.5) G24(-7.63,1.5) G26(-8.496,1.5) G28(-9.362,1.5) G30(-10.228,1.5) G32(-11.094,1.5) G34(-11.96,1.5) H4(-0.75,1.732) H6(-1.25,1.732) H8(-1.75,1.732) H10(-2.25,1.732) H13(-2.867,1.75) H15(-3.733,1.75) H17(-4.599,1.75) H19(-5.465,1.75) H21(-6.331,1.75) H23(-7.197,1.75) H25(-8.063,1.75) H27(-8.929,1.75) H29(-9.795,1.75) H31(-10.661,1.75) H33(-11.527,1.75) H35(-12.393,1.75) H36(-12.984,1.732) H38(-13.484,1.732) H40(-13.984,1.732) H42(-14.484,1.732) H44(-14.984,1.732) J3(-0.5,2.165) J5(-1,2.165) J7(-1.5,2.165) J9(-2,2.165) J14(-3.3,2) J16(-4.166,2) J18(-5.032,2) J20(-5.898,2) J22(-6.764,2) J24(-7.63,2) J26(-8.496,2) J28(-9.362,2) J30(-10.228,2) J32(-11.094,2) J34(-11.96,2) J37(-13.234,2.165) J39(-13.734,2.165) J41(-14.234,2.165) J43(-14.734,2.165) K13(-2.867,2.25) K15(-3.733,2.25) K17(-4.599,2.25) K19(-5.465,2.25) K21(-6.331,2.25) K23(-7.197,2.25) K25(-8.063,2.25) K27(-8.929,2.25) K29(-9.795,2.25) K31(-10.661,2.25) K33(-11.527,2.25) K35(-12.393,2.25) L2(-0.25,2.598) L4(-0.75,2.598) L6(-1.25,2.598) L8(-1.75,2.598) L10(-2.25,2.598) L14(-3.3,2.5) L16(-4.166,2.5) L18(-5.032,2.5) L20(-5.898,2.5) L22(-6.764,2.5) L24(-7.63,2.5) L26(-8.496,2.5) L28(-9.362,2.5) L30(-10.228,2.5) L32(-11.094,2.5) L34(-11.96,2.5) L36(-12.843,2.5) L38(-13.484,2.598) L40(-13.984,2.598) L42(-14.484,2.598) L44(-14.984,2.598) M13(-2.867,2.75) M15(-3.733,2.75) M17(-4.599,2.75) M19(-5.465,2.75) M21(-6.331,2.75) M23(-7.197,2.75) M25(-8.063,2.75) M27(-8.929,2.75) M29(-9.795,2.75) M31(-10.661,2.75) M33(-11.527,2.75) M35(-12.393,2.75) N3(-0.5,3.031) N5(-1,3.031) N7(-1.5,3.031) N9(-2,3.031) N14(-3.3,3) N16(-4.166,3) N18(-5.032,3) N20(-5.898,3) N22(-6.764,3) N24(-7.63,3) N26(-8.496,3) N28(-9.362,3) N30(-10.228,3) N32(-11.094,3) N34(-11.96,3) N36(-13.094,3.029) N39(-13.734,3.031) N41(-14.234,3.031) N43(-14.734,3.031) P13(-2.867,3.25) P15(-3.733,3.25) P17(-4.599,3.25) P19(-5.465,3.25) P21(-6.331,3.25) P23(-7.197,3.25) P25(-8.063,3.25) P27(-8.929,3.25) P29(-9.795,3.25) P31(-10.661,3.25) P33(-11.527,3.25) P35(-12.393,3.25) R2(-0.25,3.464) R4(-0.75,3.464) R6(-1.25,3.464) R8(-1.75,3.464) R10(-2.25,3.464) R14(-3.3,3.5) R16(-4.166,3.5) R18(-5.032,3.5) R20(-5.898,3.5) R22(-6.764,3.5) R24(-7.63,3.5) R26(-8.496,3.5) R28(-9.362,3.5) R30(-10.228,3.5) R32(-11.094,3.5) R34(-11.96,3.5) R36(-12.924,3.5) R38(-13.484,3.464) R40(-13.984,3.464) R42(-14.484,3.464) R44(-14.984,3.464) T3(-0.5,3.897) T5(-1,3.897) T7(-1.5,3.897) T9(-2,3.897) T13(-2.867,3.75) T15(-3.733,3.75) T17(-4.599,3.75) T19(-5.465,3.75) T21(-6.331,3.75) T23(-7.197,3.75) T25(-8.063,3.75) T27(-8.929,3.75) T29(-9.795,3.75) T31(-10.661,3.75) T33(-11.527,3.75) T35(-12.624,3.96) T37(-13.234,3.897) T39(-13.734,3.897) T41(-14.234,3.897) T43(-14.734,3.897) U14(-3.3,4) U16(-4.166,4) U18(-5.032,4) U20(-5.898,4) U22(-6.764,4) U24(-7.63,4) U26(-8.496,4) U28(-9.362,4) U30(-10.228,4) U32(-11.094,4) U34(-11.96,4) V2(-0.25,4.33) V4(-0.75,4.33) V6(-1.25,4.33) V8(-1.75,4.33) V10(-2.25,4.33) V12(-2.75,4.25) V15(-3.747,4.277) V17(-4.577,4.329) V36(-12.984,4.33) V38(-13.484,4.33) V40(-13.984,4.33) V42(-14.484,4.33) V44(-14.984,4.33) W3(-0.5,4.763) W5(-1,4.763) W7(-1.5,4.763) W9(-2,4.763) W12(-2.945,4.73) W14(-3.447,4.707) W16(-4.177,4.629) W17(-4.607,4.947) W18(-5.107,4.496) W19(-5.707,4.491) W21(-6.307,4.491) W22(-6.859,4.491) W24(-7.459,4.491) W25(-8.059,4.491) W26(-8.611,4.491) W28(-9.211,4.491) W29(-9.811,4.491) W30(-10.363,4.491) W32(-10.963,4.491) W33(-11.563,4.491) W34(-12.115,4.491) W35(-12.734,4.763) W37(-13.234,4.763) W39(-13.734,4.763) W41(-14.234,4.763) W43(-14.734,4.763) Y2(-0.25,5.196) Y4(-0.75,5.196) Y6(-1.25,5.196) Y8(-1.75,5.196) Y10(-2.25,5.196) Y12(-2.75,5.196) Y14(-3.25,5.196) Y16(-3.967,5.146) Y18(-5.107,5.099) Y19(-5.707,5.099) Y21(-6.307,5.099) Y22(-6.859,5.099) Y24(-7.459,5.099) Y25(-8.059,5.099) Y26(-8.611,5.099) Y28(-9.211,5.099) Y29(-9.811,5.099) Y30(-10.363,5.099) Y32(-10.963,5.099) Y33(-11.563,5.099) Y34(-12.115,5.099) Y36(-12.984,5.196) Y38(-13.484,5.196) Y40(-13.984,5.196) Y42(-14.484,5.196) Y44(-14.984,5.196)
BELLW_80148-1721_67P-T
  round 1.092 hole 1.092 unplated: (-1.75,-1.7)
  round 1.6 hole 1.6 unplated: (20.25,-1.7)
  oval 0.305x1.499 smd: 1(0,0) 3(0.5,0) 5(1,0) 7(1.5,0) 9(4,0) 11(4.5,0) 13(5,0) 15(5.5,0) 17(6,0) 19(6.5,0) 21(7,0) 23(7.5,0) 25(8,0) 27(8.5,0) 29(9,0) 31(9.5,0) 33(10,0) 35(10.5,0) 37(11,0) 39(11.5,0) 41(12,0) 43(12.5,0) 45(13,0) 47(13.5,0) 49(14,0) 51(14.5,0) 53(15,0) 55(15.5,0) 57(16,0) 59(16.5,0) 61(17,0) 63(17.5,0) 65(18,0) 67(18.5,0)
  round 0.762 hole 0.508: 2(0.25,-2.59) 4(0.75,-1.79) 6(1.25,-2.59) 8(3.75,-1.79) 10(4.25,-2.59) 12(4.75,-1.79) 14(5.25,-2.59) 16(5.75,-1.79) 18(6.25,-2.59) 20(6.75,-1.79) 22(7.25,-2.59) 24(7.75,-1.79) 26(8.25,-2.59) 28(8.75,-1.79) 30(9.25,-2.59) 32(9.75,-1.79) 34(10.25,-2.59) 36(10.75,-1.79) 38(11.25,-2.59) 40(11.75,-1.79) 42(12.25,-2.59) 44(12.75,-1.79) 46(13.25,-2.59) 48(13.75,-1.79) 50(14.25,-2.59) 52(14.75,-1.79) 54(15.25,-2.59) 56(15.75,-1.79) 58(16.25,-2.59) 60(16.75,-1.79) 62(17.25,-2.59) 64(17.75,-1.79) 66(18.25,-2.59)
  oval 0.889x2.057 hole 0.508x1.753: 68(-2,-5.75) 69(20.5,-5.75)
BELLW_80149-2021_67P-T
  round 1.092 hole 1.092 unplated: (-0.75,-5.275)
  round 1.6 hole 1.6 unplated: (19.25,-5.275)
  oval 0.305x1.549 smd: 1(0,0) 2(0.25,-7.55) 3(0.5,0) 4(0.75,-7.55) 5(1,0) 6(1.25,-7.55) 7(1.5,0) 8(1.75,-7.55) 9(2,0) 10(2.25,-7.55) 11(2.5,0) 12(4.75,-7.55) 13(5,0) 14(5.25,-7.55) 15(5.5,0) 16(5.75,-7.55) 17(6,0) 18(6.25,-7.55) 19(6.5,0) 20(6.75,-7.55) 21(7,0) 22(7.25,-7.55) 23(7.5,0) 24(7.75,-7.55) 25(8,0) 26(8.25,-7.55) 27(8.5,0) 28(8.75,-7.55) 29(9,0) 30(9.25,-7.55) 31(9.5,0) 32(9.75,-7.55) 33(10,0) 34(10.25,-7.55) 35(10.5,0) 36(10.75,-7.55) 37(11,0) 38(11.25,-7.55) 39(11.5,0) 40(11.75,-7.55) 41(12,0) 42(12.25,-7.55) 43(12.5,0) 44(12.75,-7.55) 45(13,0) 46(13.25,-7.55) 47(13.5,0) 48(13.75,-7.55) 49(14,0) 50(14.25,-7.55) 51(14.5,0) 52(14.75,-7.55) 53(15,0) 54(15.25,-7.55) 55(15.5,0) 56(15.75,-7.55) 57(16,0) 58(16.25,-7.55) 59(16.5,0) 60(16.75,-7.55) 61(17,0) 62(17.25,-7.55) 63(17.5,0) 64(17.75,-7.55) 65(18,0) 66(18.25,-7.55) 67(18.5,0)
  rect 1.194x2.743 smd: 68(-1.1,-0.775) 69(19.6,-0.775)
BQ24777RUYR_WQFN28_4X4
  oval 0.889x0.203 smd: 1(0,0) 2(0,-0.4) 3(0,-0.8) 4(0,-1.2) 5(0,-1.6) 6(0,-2) 7(0,-2.4) 15(4.1,-2.4) 16(4.1,-2) 17(4.1,-1.6) 18(4.1,-1.2) 19(4.1,-0.8) 20(4.1,-0.4) 21(4.1,0)
  oval 0.203x0.889 smd: 8(0.85,-3.25) 9(1.25,-3.25) 10(1.65,-3.25) 11(2.05,-3.25) 12(2.45,-3.25) 13(2.85,-3.25) 14(3.25,-3.25) 22(3.25,0.85) 23(2.85,0.85) 24(2.45,0.85) 25(2.05,0.85) 26(1.65,0.85) 27(1.25,0.85) 28(0.85,0.85)
  rect 2.591x2.591 smd: 29(2.05,-1.2)
BSS138-G_SOT23-3
  oval 1.016x1.524 smd: 1(0,0) 2(0.965,2.083) 3(-0.965,2.083)
C_0402
  rect 0.508x0.559 smd: 1(0,0) 2(0.914,0)
C_0603
  rect 0.635x0.889 smd: 1(0,0) 2(1.397,0)
C_0805
  rect 0.813x1.397 smd: 1(0,0) 2(1.702,0)
C_B2
  rect 1.346x2.692 smd: 1(0,0) 2(-2.75,0)
C_D2
  rect 2.388x2.794 smd: 1(0,0) 2(6.4,0)
C_D2E
  rect 2.388x2.896 smd: 1(0,0) 2(6.1,0)
C_X
  rect 1.803x2.896 smd: 1(0,0) 2(6,0)
CSD87312Q3E_SON8-4
  rect 2.388x0.66 smd: 1(0,0)
  rect 0.432x0.66 smd: 2(0.975,2.95)
  rect 1.753x0.66 smd: 3(-0.325,2.95)
  custom 0.475x0.475 smd: 4(0,1.475)
CSD87330Q3D_SON8-7
  oval 1.092x0.66 smd: 1(0,0)
  oval 0.432x0.66 smd: 2(0.975,0) 3(1.625,0) 4(1.625,2.95) 5(0.975,2.95) 6(0.325,2.95) 7(-0.325,2.95)
  custom 0.475x0.475 smd: 8(0.65,1.475)
CSD87351Q5D_SON8-7
  oval 1.93x0.838 smd: 1(0,0)
  oval 0.66x0.838 smd: 2(1.905,0) 3(3.175,0) 4(3.175,5.39) 5(1.905,5.39) 6(0.635,5.39) 7(-0.635,5.39)
  custom 0.87x0.87 smd: 8(1.27,2.695)
DCX124EK-7-F_SC74R-6
  oval 0.559x0.787 smd: 1(0,0) 2(-0.95,0) 3(-1.9,0) 4(-1.9,2.4) 5(-0.95,2.4) 6(0,2.4)
DMN65D8LW-7_SOT323-3
  oval 0.711x0.889 smd: 1(0,0) 2(-0.65,-1.9) 3(0.65,-1.9)
DMN66D0LDW-7_SOT363-6
  oval 0.432x0.61 smd: 1(0,0) 2(0.65,0) 3(1.3,0) 4(1.3,1.9) 5(0.65,1.9) 6(0,1.9)
E-T_3703K-F04N-03R_4P
  oval 0.61x1.549 smd: 1(0,0) 2(1,0) 3(2,0) 4(3,0)
  rect 1.194x2.007 smd: 5(-1.3,-3.775) 6(4.3,-3.775)
E-T_6601K-Y61N-04L_61P
  oval 0.305x1.245 smd: 1(0,0) 3(0.6,0) 5(1.2,0) 7(1.8,0) 9(2.4,0) 11(3,0) 13(3.6,0) 15(4.2,0) 17(4.8,0) 19(5.4,0) 21(6,0) 23(6.6,0) 25(7.2,0) 27(7.8,0) 29(8.4,0) 31(9,0) 33(9.6,0) 35(10.2,0) 37(10.8,0) 39(11.4,0) 41(12,0) 43(12.6,0) 45(13.2,0) 47(13.8,0) 49(14.4,0) 51(15,0) 53(15.6,0) 55(16.2,0) 57(16.8,0) 59(17.4,0) 61(18,0)
  oval 0.305x0.94 smd: 2(0.3,3.25) 4(0.9,3.25) 6(1.5,3.25) 8(2.1,3.25) 10(2.7,3.25) 12(3.3,3.25) 14(3.9,3.25) 16(4.5,3.25) 18(5.1,3.25) 20(5.7,3.25) 22(6.3,3.25) 24(6.9,3.25) 26(7.5,3.25) 28(8.1,3.25) 30(8.7,3.25) 32(9.3,3.25) 34(9.9,3.25) 36(10.5,3.25) 38(11.1,3.25) 40(11.7,3.25) 42(12.3,3.25) 44(12.9,3.25) 46(13.5,3.25) 48(14.1,3.25) 50(14.7,3.25) 52(15.3,3.25) 54(15.9,3.25) 56(16.5,3.25) 58(17.1,3.25) 60(17.7,3.25)
  rect 0.305x1.143 smd: 62(-0.65,0.6) 63(18.65,0.6)
E-T_6705K-Y18N-00L_18P
  oval 0.305x1.092 smd: 1(0,0) 2(-0.5,0) 3(-1,0) 4(-1.5,0) 5(-2,0) 6(-2.5,0) 7(-3,0) 8(-3.5,0) 9(-4,0) 10(-4.5,0) 11(-5,0) 12(-5.5,0) 13(-6,0) 14(-6.5,0) 15(-7,0) 16(-7.5,0) 17(-8,0) 18(-8.5,0)
  rect 0.991x2.007 smd: 19(2.1,-3.15) 20(-10.6,-3.15)
E-T_6705K-Y20N-00L_20P
  oval 0.305x1.092 smd: 1(0,0) 2(-0.5,0) 3(-1,0) 4(-1.5,0) 5(-2,0) 6(-2.5,0) 7(-3,0) 8(-3.5,0) 9(-4,0) 10(-4.5,0) 11(-5,0) 12(-5.5,0) 13(-6,0) 14(-6.5,0) 15(-7,0) 16(-7.5,0) 17(-8,0) 18(-8.5,0) 19(-9,0) 20(-9.5,0)
  rect 0.991x2.007 smd: 21(2.1,-3.15) 22(-11.6,-3.15)
E-T_6718K-Y24N-20L_24P-T
  oval 0.305x0.991 smd: 1(0,0) 2(0.5,0) 3(1,0) 4(1.5,0) 5(2,0) 6(2.5,0) 7(3,0) 8(3.5,0) 9(4,0) 10(4.5,0) 11(5,0) 12(5.5,0) 13(6,0) 14(6.5,0) 15(7,0) 16(7.5,0) 17(8,0) 18(8.5,0) 19(9,0) 20(9.5,0) 21(10,0) 22(10.5,0) 23(11,0) 24(11.5,0)
  rect 0.406x0.787 smd: 25(-1,-2.6) 26(12.5,-2.6)
EMIST_SUL-12A2M_1P
  rect 6.909x1.194 smd: 1(0,0)
ESD207-B1-02EL_TSLP-2-19-2
  rect 0.356x0.61 smd: 1(0,0) 2(0.65,0)
FDV301N_NL_SOT23-3
  oval 1.016x1.524 smd: 1(0,0) 2(0.965,2.083) 3(-0.965,2.083)
FIDUCIAL_C40M80
  round 1.016 smd: 1(0,0)
FOX_GS73091-10272M-7H_9P
  rect 0.66x5.004 smd: 1(0,0) 2(-1.5,0) 3(-3,0) 4(-4.5,0) 5(-6,0) 6(-7.5,0) 7(-9,0) 8(-10.5,0) 9(-12,0)
  rect 2.489x2.997 smd: 10(-14.5,4.45) 11(2.5,4.45)
G601A31U_ADFN6_1P5X1P5
  oval 0.254x1.092 smd: 1(0,0)
  oval 0.254x0.991 smd: 2(0.5,-0.051) 3(1,-0.051) 4(1,1.449) 5(0.5,1.449) 6(0,1.449)
G5616ARZ1U_TQFN20_3X3
  oval 0.203x1.016 smd: 1(0,0) 2(0.4,0) 3(0.8,0) 4(1.2,0) 5(1.6,0) 11(1.6,2.975) 12(1.2,2.975) 13(0.8,2.975) 14(0.4,2.975) 15(0,2.975)
  oval 1.016x0.203 smd: 6(2.288,0.688) 7(2.288,1.088) 8(2.288,1.488) 9(2.288,1.888) 10(2.288,2.288) 16(-0.688,2.288) 17(-0.688,1.888) 18(-0.688,1.488) 19(-0.688,1.088) 20(-0.688,0.688)
  rect 1.6x1.6 smd: 21(0.8,1.488)
H_1P2
  round 1.702 hole 1.194: 1(0,0)
H_3P7
  round 4.216 hole 3.708: 1(0,0)
H_4P0N
  round 3.988 hole 3.988 unplated: (0,0)
H_4P0X5P0
  oval 4.496x5.512 hole 3.988x5.004: 1(0,0)
H_4P6
  round 5.105 hole 4.597: 1(0,0)
HRS_FH29DJ-70S-0P2SHW-05_70P-T
  oval 0.203x1.245 smd: 1(0,0) 3(0.4,0) 5(0.8,0) 7(1.2,0) 9(1.6,0) 11(2,0) 13(2.4,0) 15(2.8,0) 17(3.2,0) 19(3.6,0) 21(4,0) 23(4.4,0) 25(4.8,0) 27(5.2,0) 29(5.6,0) 31(6,0) 33(6.4,0) 35(6.8,0) 37(7.2,0) 39(7.6,0) 41(8,0) 43(8.4,0) 45(8.8,0) 47(9.2,0) 49(9.6,0) 51(10,0) 53(10.4,0) 55(10.8,0) 57(11.2,0) 59(11.6,0) 61(12,0) 63(12.4,0) 65(12.8,0) 67(13.2,0) 69(13.6,0)
  oval 0.203x0.838 smd: 2(0,3.9) 4(0.4,3.9) 6(0.8,3.9) 8(1.2,3.9) 10(1.6,3.9) 12(2,3.9) 14(2.4,3.9) 16(2.8,3.9) 18(3.2,3.9) 20(3.6,3.9) 22(4,3.9) 24(4.4,3.9) 26(4.8,3.9) 28(5.2,3.9) 30(5.6,3.9) 32(6,3.9) 34(6.4,3.9) 36(6.8,3.9) 38(7.2,3.9) 40(7.6,3.9) 42(8,3.9) 44(8.4,3.9) 46(8.8,3.9) 48(9.2,3.9) 50(9.6,3.9) 52(10,3.9) 54(10.4,3.9) 56(10.8,3.9) 58(11.2,3.9) 60(11.6,3.9) 62(12,3.9) 64(12.4,3.9) 66(12.8,3.9) 68(13.2,3.9) 70(13.6,3.9)
  rect 0.356x0.94 smd: 71(-0.608,0.195) 72(14.207,0.195)
IP4223CZ6_SO6-6
  oval 0.508x1.422 smd: 1(0,0) 2(0.95,0) 3(1.9,0) 4(1.9,2.35) 5(0.95,2.35) 6(0,2.35)
ISL95813HRZ-T_QFN20_3X4
  oval 0.254x0.889 smd: 1(0,0) 2(0.5,0) 3(1,0) 4(1.5,0) 5(2,0) 6(2.5,0) 11(2.5,3.1) 12(2,3.1) 13(1.5,3.1) 14(1,3.1) 15(0.5,3.1) 16(0,3.1)
  oval 0.889x0.254 smd: 7(3.3,0.8) 8(3.3,1.3) 9(3.3,1.8) 10(3.3,2.3) 17(-0.8,2.3) 18(-0.8,1.8) 19(-0.8,1.3) 20(-0.8,0.8)
  rect 2.642x1.651 smd: 21(1.25,1.55)
JUMP_43X39
  custom 0.191x0.191 smd: 1(0,0) 2(0.914,0)
JUMP_43X118
  custom 0.187x0.187 smd: 1(0,0) 2(1.1,0)
KC_FBMA-L11-160808-800LMT_2P
  rect 0.889x1.092 smd: 1(0,0) 2(1.5,0)
KC_FBMA-L11-201209-121LMA50_2P
  rect 0.991x1.702 smd: 1(0,0) 2(1.5,0)
L_1812-1806
  oval 1.016x3.708 smd: 1(0,0) 2(4.013,0)
LM393DMR2G_MICRO8
  oval 0.381x1.041 smd: 1(0,0) 2(0.65,0) 3(1.3,0) 4(1.95,0) 5(1.95,4.24) 6(1.3,4.24) 7(0.65,4.24) 8(0,4.24)
M74VHC1GT00DFT2G_SC70-5
  oval 0.406x0.508 smd: 1(0,0) 2(0.65,0) 3(1.3,0) 4(1.3,1.9) 5(0,1.9)
MAG_MMD-06BD-1R0M-X2L_2P
  rect 2.159x3.505 smd: 1(0,0) 2(5.85,0)
MAG_MMD-06BD-2R2M-X2L_2P
  rect 2.159x3.505 smd: 1(0,0) 2(5.85,0)
MAG_MMD-06BD-R22MEV1L_4P
  custom 0.686x0.686 smd: 1(0,0) 4(8.509,0)
  rect 2.362x0.508 smd: 2(1.448,0) 3(7.061,0)
MEC1641-PZV_TFBGA_144P
  round 0.254 smd: A1(0,0) A2(0.5,0) A3(1,0) A4(1.5,0) A5(2.001,0) A6(2.501,0) A7(3.001,0) A8(3.501,0) A9(4.001,0) A10(4.501,0) A11(5.001,0) A12(5.501,0) A13(6.002,0) B1(0,-0.5) B2(0.5,-0.5) B3(1,-0.5) B4(1.5,-0.5) B5(2.001,-0.5) B6(2.501,-0.5) B7(3.001,-0.5) B8(3.501,-0.5) B9(4.001,-0.5) B10(4.501,-0.5) B11(5.001,-0.5) B12(5.501,-0.5) B13(6.002,-0.5) C1(0,-1) C2(0.5,-1) C3(1,-1) C4(1.5,-1) C5(2.001,-1) C6(2.501,-1) C7(3.001,-1) C8(3.501,-1) C9(4.001,-1) C10(4.501,-1) C11(5.001,-1) C12(5.501,-1) C13(6.002,-1) D1(0,-1.5) D2(0.5,-1.5) D3(1,-1.5) D4(1.5,-1.5) D5(2.001,-1.5) D6(2.501,-1.5) D7(3.001,-1.5) D8(3.501,-1.5) D9(4.001,-1.5) D10(4.501,-1.5) D11(5.001,-1.5) D12(5.501,-1.5) D13(6.002,-1.5) E1(0,-2.001) E2(0.5,-2.001) E3(1,-2.001) E4(1.5,-2.001) E10(4.501,-2.001) E11(5.001,-2.001) E12(5.501,-2.001) E13(6.002,-2.001) F1(0,-2.501) F2(0.5,-2.501) F3(1,-2.501) F4(1.5,-2.501) F10(4.501,-2.501) F11(5.001,-2.501) F12(5.501,-2.501) F13(6.002,-2.501) G1(0,-3.001) G2(0.5,-3.001) G3(1,-3.001) G4(1.5,-3.001) G10(4.501,-3.001) G11(5.001,-3.001) G12(5.501,-3.001) G13(6.002,-3.001) H1(0,-3.501) H2(0.5,-3.501) H3(1,-3.501) H4(1.5,-3.501) H10(4.501,-3.501) H11(5.001,-3.501) H12(5.501,-3.501) H13(6.002,-3.501) J1(0,-4.001) J2(0.5,-4.001) J3(1,-4.001) J4(1.5,-4.001) J10(4.501,-4.001) J11(5.001,-4.001) J12(5.501,-4.001) J13(6.002,-4.001) K1(0,-4.501) K2(0.5,-4.501) K3(1,-4.501) K4(1.5,-4.501) K5(2.001,-4.501) K6(2.501,-4.501) K7(3.001,-4.501) K8(3.501,-4.501) K9(4.001,-4.501) K10(4.501,-4.501) K11(5.001,-4.501) K12(5.501,-4.501) K13(6.002,-4.501) L1(0,-5.001) L2(0.5,-5.001) L3(1,-5.001) L4(1.5,-5.001) L5(2.001,-5.001) L6(2.501,-5.001) L7(3.001,-5.001) L8(3.501,-5.001) L9(4.001,-5.001) L10(4.501,-5.001) L11(5.001,-5.001) L12(5.501,-5.001) L13(6.002,-5.001) M1(0,-5.501) M2(0.5,-5.501) M3(1,-5.501) M4(1.5,-5.501) M5(2.001,-5.501) M6(2.501,-5.501) M7(3.001,-5.501) M8(3.501,-5.501) M9(4.001,-5.501) M10(4.501,-5.501) M11(5.001,-5.501) M12(5.501,-5.501) M13(6.002,-5.501) N1(0,-6.002) N2(0.5,-6.002) N3(1,-6.002) N4(1.5,-6.002) N5(2.001,-6.002) N6(2.501,-6.002) N7(3.001,-6.002) N8(3.501,-6.002) N9(4.001,-6.002) N10(4.501,-6.002) N11(5.001,-6.002) N12(5.501,-6.002) N13(6.002,-6.002)
MMBT3904WH_SOT323-3
  oval 0.61x0.787 smd: 1(0,0) 2(-0.65,-1.6) 3(0.65,-1.6)
MMST3904-7-F_SOT323-3
  oval 0.711x0.889 smd: 1(0,0) 2(0.65,1.9) 3(-0.65,1.9)
MT41J256M16RE-15E-D_FBGA_96P
  round 0.343 smd: A1(0,0) A2(0.8,0) A3(1.6,0) A7(4.8,0) A8(5.6,0) A9(6.4,0) B1(0,-0.8) B2(0.8,-0.8) B3(1.6,-0.8) B7(4.8,-0.8) B8(5.6,-0.8) B9(6.4,-0.8) C1(0,-1.6) C2(0.8,-1.6) C3(1.6,-1.6) C7(4.8,-1.6) C8(5.6,-1.6) C9(6.4,-1.6) D1(0,-2.4) D2(0.8,-2.4) D3(1.6,-2.4) D7(4.8,-2.4) D8(5.6,-2.4) D9(6.4,-2.4) E1(0,-3.2) E2(0.8,-3.2) E3(1.6,-3.2) E7(4.8,-3.2) E8(5.6,-3.2) E9(6.4,-3.2) F1(0,-4) F2(0.8,-4) F3(1.6,-4) F7(4.8,-4) F8(5.6,-4) F9(6.4,-4) G1(0,-4.8) G2(0.8,-4.8) G3(1.6,-4.8) G7(4.8,-4.8) G8(5.6,-4.8) G9(6.4,-4.8) H1(0,-5.6) H2(0.8,-5.6) H3(1.6,-5.6) H7(4.8,-5.6) H8(5.6,-5.6) H9(6.4,-5.6) J1(0,-6.4) J2(0.8,-6.4) J3(1.6,-6.4) J7(4.8,-6.4) J8(5.6,-6.4) J9(6.4,-6.4) K1(0,-7.2) K2(0.8,-7.2) K3(1.6,-7.2) K7(4.8,-7.2) K8(5.6,-7.2) K9(6.4,-7.2) L1(0,-8) L2(0.8,-8) L3(1.6,-8) L7(4.8,-8) L8(5.6,-8) L9(6.4,-8) M1(0,-8.8) M2(0.8,-8.8) M3(1.6,-8.8) M7(4.8,-8.8) M8(5.6,-8.8) M9(6.4,-8.8) N1(0,-9.6) N2(0.8,-9.6) N3(1.6,-9.6) N7(4.8,-9.6) N8(5.6,-9.6) N9(6.4,-9.6) P1(0,-10.4) P2(0.8,-10.4) P3(1.6,-10.4) P7(4.8,-10.4) P8(5.6,-10.4) P9(6.4,-10.4) R1(0,-11.2) R2(0.8,-11.2) R3(1.6,-11.2) R7(4.8,-11.2) R8(5.6,-11.2) R9(6.4,-11.2) T1(0,-12) T2(0.8,-12) T3(1.6,-12) T7(4.8,-12) T8(5.6,-12) T9(6.4,-12)
MURAT_BLM15PX181SN1D_2P
  rect 0.508x0.762 smd: 1(0,0) 2(0.75,0)
MURAT_DLW21HN900HQ2L_4P
  rect 0.889x0.356 smd: 1(0,0) 2(1.7,0) 3(1.7,0.85) 4(0,0.85)
MURAT_LQM2MPN2R2NG0L_2P
  rect 0.787x1.803 smd: 1(0,0) 2(1.6,0)
MURAT_LQM21PN2R2MC0D_2P
  rect 1.143x1.194 smd: 1(0,0) 2(2.35,0)
NCP4545IMNTWG_QFN18_3X3
  oval 0.254x0.94 smd: 1(0,0) 2(0.5,0) 3(1,0) 4(1.5,0) 10(1.5,3.05) 11(1,3.05) 12(0.5,3.05) 13(0,3.05)
  oval 0.94x0.254 smd: 5(2.275,0.525) 6(2.275,1.025) 7(2.275,1.525) 8(2.275,2.025) 9(2.275,2.525) 14(-0.775,2.525) 15(-0.775,2.025) 16(-0.775,1.525) 17(-0.775,1.025) 18(-0.775,0.525)
  rect 1.854x1.854 smd: 19(0.75,1.525)
PJSOT24CW_SOT323-3
  oval 0.66x0.864 smd: 1(0,0) 2(-0.65,-1.85) 3(0.65,-1.85)
PS8713BTQFN24GTR2_TQFN24_4X4
  oval 0.254x0.889 smd: 1(0,0) 2(0.5,0) 3(1,0) 4(1.5,0) 5(2,0) 6(2.5,0) 13(2.5,4.1) 14(2,4.1) 15(1.5,4.1) 16(1,4.1) 17(0.5,4.1) 18(0,4.1)
  oval 0.889x0.254 smd: 7(3.3,0.8) 8(3.3,1.3) 9(3.3,1.8) 10(3.3,2.3) 11(3.3,2.8) 12(3.3,3.3) 19(-0.8,3.3) 20(-0.8,2.8) 21(-0.8,2.3) 22(-0.8,1.8) 23(-0.8,1.3) 24(-0.8,0.8)
  rect 2.692x2.692 smd: 25(1.25,2.05)
R0402_0OHM
  rect 0.508x0.559 smd: 1(0,0) 2(0.914,0)
R0603_0OHM
  rect 0.635x0.889 smd: 1(0,0) 2(1.397,0)
R0805_0OHM
  rect 0.813x1.397 smd: 1(0,0) 2(1.702,0)
R1206_0OHM
  rect 1.016x1.651 smd: 1(0,0) 2(2.667,0)
R_0402
  rect 0.508x0.559 smd: 1(0,0) 2(0.914,0)
R_0603
  rect 0.635x0.889 smd: 1(0,0) 2(1.397,0)
R_0805
  rect 0.813x1.397 smd: 1(0,0) 2(1.702,0)
R_1206
  rect 1.016x1.651 smd: 1(0,0) 2(2.667,0)
R_1206_4P-D
  custom 0.445x0.445 smd: 1(0,0) 4(5.004,0)
  custom 0.114x0.114 smd: 2(1.194,0) 3(3.81,0)
RP_0804_8P4R
  oval 0.66x0.254 smd: 1(0,0) 2(0,-0.5) 3(0,-1) 4(0,-1.5) 5(1.15,-1.5) 6(1.15,-1) 7(1.15,-0.5) 8(1.15,0)
SDMK0340L-7-F_SOD323-2
  rect 1.346x0.66 smd: 1(0,0) 2(2.4,0)
SHORTPADS
  custom 0.19x0.19 smd: 1(-0.483,0) 2(0.483,0)
SI1553CDL-T1-GE3_SC70-6
  oval 0.406x0.66 smd: 1(0,0) 2(0.65,0) 3(1.3,0) 4(1.3,1.791) 5(0.65,1.791) 6(0,1.791)
SI2303CDS-T1-GE3_SOT23-3
  oval 1.016x1.524 smd: 1(0,0) 2(0.965,2.083) 3(-0.965,2.083)
SI3457BDV-T1-E3_TSOP6
  oval 0.508x1.448 smd: 1(0,0) 2(1,0) 3(2,0) 4(2,2.425) 5(1,2.425) 6(0,2.425)
SIS412DN-T1-GE3_POWERPAK8-5
  oval 0.406x0.991 smd: 1(0,0) 2(0.66,0) 3(1.32,0) 4(1.98,0)
  custom 0.559x0.559 smd: 5(0.99,2.247)
SN74AHC1G04DCKR_SOT23-5
  oval 0.356x1.219 smd: 1(0,0) 2(0.65,0) 3(1.3,0) 4(1.3,1.675) 5(0,1.675)
SN74AHC1G08DCKR_SC70-5
  oval 0.381x1.295 smd: 1(0,0.15) 2(0.65,0.15) 3(1.3,0.15) 4(1.3,1.89) 5(0,1.89)
SSM3K7002FU_SC70-3
  oval 0.508x0.991 smd: 1(0,0) 2(0.65,1.9) 3(-0.65,1.9)
SW_NTC033-XK1K-A160T_4P
  rect 0.991x0.889 smd: 1(0,0) 2(3.85,0) 3(0,-3.9) 4(3.85,-3.9)
SY8206DQNC_QFN10_3X3
  oval 0.254x0.61 smd: 1(0,0) 2(0.45,0) 3(0.9,0) 4(1.35,0) 5(1.8,0) 6(2.25,0)
  rect 1.168x0.254 smd: 7(2.19,-0.675)
  rect 0.914x2.007 smd: 8(2.065,-2)
  custom 0.482x0.482 smd: 9(1.077,-1.775)
  rect 0.813x1.168 smd: 10(0.137,-1.587)
TAI-T_HCB1608KF-121T3_L0603_2P
  rect 0.991x0.787 smd: 1(0,0) 2(1.6,0)
TAI-T_HCB2012KF-121T50_2P
  rect 0.991x0.991 smd: 1(0,0) 2(2,0)
TLV62150RGTR_QFN16_3X3
  oval 0.254x1.016 smd: 1(0,0) 2(0.5,0) 3(1,0) 4(1.5,0) 9(1.5,2.975) 10(1,2.975) 11(0.5,2.975) 12(0,2.975)
  oval 1.016x0.254 smd: 5(2.238,0.738) 6(2.238,1.238) 7(2.238,1.738) 8(2.238,2.238) 13(-0.738,2.238) 14(-0.738,1.738) 15(-0.738,1.238) 16(-0.738,0.738)
  rect 1.702x1.702 smd: 17(0.75,1.488)
TOKO_1239AS-H-2R2N-P2_2P
  rect 0.787x2.007 smd: 1(0,0) 2(2,0)
TPC12
  round 0.305 smd: 1(0,0)
TPS22966DPUR_SON14_2X3
  oval 0.203x0.762 smd: 1(0,0) 2(0.4,0) 3(0.8,0) 4(1.2,0) 5(1.6,0) 6(2,0) 7(2.4,0) 8(2.4,2.05) 9(2,2.05) 10(1.6,2.05) 11(1.2,2.05) 12(0.8,2.05) 13(0.4,2.05) 14(0,2.05)
  rect 2.489x0.889 smd: 15(1.2,1.025)
TPS51285BRUKR_QFN20_3X3
  oval 0.203x1.016 smd: 1(0,0) 2(0.4,0) 3(0.8,0) 4(1.2,0) 5(1.6,0) 11(1.6,2.975) 12(1.2,2.975) 13(0.8,2.975) 14(0.4,2.975) 15(0,2.975)
  oval 1.016x0.203 smd: 6(2.288,0.688) 7(2.288,1.088) 8(2.288,1.488) 9(2.288,1.888) 10(2.288,2.288) 16(-0.688,2.288) 17(-0.688,1.888) 18(-0.688,1.488) 19(-0.688,1.088) 20(-0.688,0.688)
  rect 1.702x1.702 smd: 21(0.8,1.488)
TVNST52302AB0_SOT523-3
  oval 0.508x0.559 smd: 1(0,0) 2(-0.5,-1.4) 3(0.5,-1.4)
TXB0104YZTR_DSBGA_12P
  round 0.254 smd: A1(0,0) A2(0.5,0) A3(1,0) B1(0,-0.5) B2(0.5,-0.5) B3(1,-0.5) C1(0,-1) C2(0.5,-1) C3(1,-1) D1(0,-1.501) D2(0.5,-1.501) D3(1,-1.501)
W25Q64FVSSIQ_SO8
  oval 0.635x1.676 smd: 1(0,0) 2(1.27,0) 3(2.54,0) 4(3.81,0) 5(3.81,7.25) 6(2.54,7.25) 7(1.27,7.25) 8(0,7.25)
Y_9H03200031_2P
  rect 0.991x1.803 smd: 1(0,0) 2(2.5,0)
Y_9H03220008_2P
  rect 0.991x1.803 smd: 1(0,0) 2(2.5,0)
Y_X3G024000DC1H_4P
  rect 1.397x1.194 smd: 1(0,0) 2(2.2,0) 3(2.2,1.7) 4(0,1.7)

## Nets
1.05V_M_EN: R342.2 R361.2 U59.3
1.05V_VR_EN: PR500.2 R343.2 R368.2 R369.2
1.05VA_PG: PR506.2 PU500.2 R222.2
1.05VS_PG: R202.2 U5.1 U37.2
1.5VS_PWROK: PR404.1 PU400.4 R240.2
1.05VS_VCCST_PG: R15.1 R201.2 RC29.1 U37.4
1.8VS_PWROK: PR409.1 PU401.4 R241.2
1.35V_B+: PC600.1 PC601.1 PC602.1 PC603.1 PL600.2 PQ600.2 PQ600.3 PQ600.4 PQ600.10 PR606.1
3.3V_NGFF1_EN: D18.3 U38.G4
3/5V_B+: PC303.1 PC313.1 PC314.1 PC315.1 PL300.2 PL304.2 PQ300.1 PQ501.1 PR900.1 PR907.1 PU300.12
+0.675VS: CD75.1 CD76.1 CD77.1 CD78.1 CD79.1 CD80.1 CD81.1 CD82.1 CD83.1 CD84.1 CD85.1 CD86.1 CD87.1 CD88.1 PJ602.2 RD29.2 RD30.2 RD31.2 RD32.2 RD33.2 RD34.2 RD35.2 RD36.2 RD37.2 RD38.2 RD39.2 RD40.2 RD41.2 RD42.2 RD43.2 RD44.2 RD45.2 RD46.2 RD47.2 RD48.2 RD49.2 RD50.2 RD51.2 RD52.2 RD53.2 RD54.2 RD55.2 RD56.2 RD57.2 RD58.2 RD59.2 RD60.2 RD61.2 RD62.2 RD63.2 RD64.2 RD65.2 RD66.2 RD67.2 RD68.2 RD69.2 RD70.2 RD71.2 RD72.2 RD73.2 RD74.2 RD75.2 RD76.2 RD77.2 RD78.2 RD79.2 RD80.2 RD83.2 RD84.2 RD85.2 RD86.2
+0.675VSP: PC605.1 PC606.1 PJ602.1 PU600.2 PU600.20
+1.5V_B+: PC401.1 PC404.1 PC405.1 PL400.2 PU400.10 PU400.11 PU400.12
+1.05V_M: C265.1 CH51.1 CH52.1 CH53.1 R344.1 R360.2 R370.1 UCPU1.AE15 UCPU1.N1 UCPU1.T1 UCPU1.W14
+1.05V_SATAMODPHY: C126.1 LH1.1 Q15.1 Q15.2 Q15.3 R10.1 R174.1
+1.05V_SATAMODPHY_D: Q18.1 R174.2
+1.05V_USB3MODPHY: C129.1 LH2.1 Q19.1 Q19.2 Q19.3 R11.1 R182.1
+1.05V_USB3MODPHY_D: Q22.1 R182.2
+1.05VA: C109.1 C122.1 C125.1 C128.1 C223.1 C263.1 L2.2 PJP500.2 Q11.5 Q15.5 Q19.5 R370.2 RH28.1 RH32.1 RH33.1 RH36.1 RH138.2 RH139.1 RH141.1 RH159.1 U28.4 U28.5 U28.9 U28.10 U28.11 U28.12 U28.13 U28.14 U28.18 U28.19 U59.1 U59.2
+1.05VDX_MODPHY: C123.1 Q11.1 Q11.2 Q11.3 R9.1 R167.1
+1.05VDX_MODPHY_D: Q14.1 R167.2
+1.05VS: C107.1 C108.2 C148.1 C221.1 C222.1 CH41.1 CH42.1 CH44.1 CH45.1 CH59.1 CH83.1 CH84.1 CH85.1 CH86.1 CH87.1 CH88.1 CH90.1 L1.1 L3.1 LH3.2 PC559.2 PR509.2 PR510.2 PR513.2 PR901.1 R154.2 R156.2 R235.1 R344.2 RH135.1 RH161.1 U38.B11 UCPU1.AE13 UCPU1.AG45 UCPU1.AH36 UCPU1.AJ16 UCPU1.AJ26 UCPU1.AJ28 UCPU1.AJ45 UCPU1.AK23 UCPU1.AK31 UCPU1.AL30 UCPU1.AL39 UCPU1.T17 UCPU1.T31 UCPU1.W22 UCPU1.Y22
+1.5VS: PJP400.2 UCPU1.AJ32
+1.05VS_VCCST: CH20.1 CH21.1 R6.1 R8.1 R201.1 RC6.2 RC11.2 RC21.2 RC32.2 RC33.1 RH135.2 UCPU1.AJ20
+1.05VS_XDP: JXDP1.43 JXDP1.44 RH161.2
+1.5VSP: PC402.1 PC403.1 PJP400.1 PL401.2 PR401.1 PU400.14
+1.05VSP: PC508.1 PC509.1 PC510.1 PC511.1 PC512.1 PJP500.1 PL501.2 PR505.1
+1.8V_B+: PC409.1 PC412.1 PC413.1 PL402.2 PU401.10 PU401.11 PU401.12
+1.8VS: PJP401.2 R151.1 R290.1 R327.1 RH140.2 U53.B2 U53.C2
+1.8VS_AUDIO: JAUD1.25 JAUD1.27 U30.13 U30.14
+1.8VSP: PC410.1 PC411.1 PJP401.1 PL403.2 PR406.1 PU401.14
+1.35V_DDR: C216.1 C217.1 C224.1 C268.1 C269.1 C270.1 C271.1 CC1.1 CC2.1 CC3.1 CC4.1 CC5.1 CC6.1 CC7.1 CC8.1 CC9.1 CC10.1 CC11.1 CD6.1 CD7.1 CD8.1 CD9.1 CD10.1 CD11.1 CD12.1 CD13.1 CD14.1 CD15.1 CD16.1 CD17.1 CD18.1 CD24.1 CD25.1 CD26.1 CD27.1 CD28.1 CD29.1 CD30.1 CD31.1 CD32.1 CD33.1 CD34.1 CD35.1 CD41.1 CD42.1 CD43.1 CD44.1 CD45.1 CD46.1 CD47.1 CD48.1 CD49.1 CD50.1 CD51.1 CD52.1 CD53.1 CD59.1 CD60.1 CD61.1 CD62.1 CD63.1 CD64.1 CD65.1 CD66.1 CD67.1 CD68.1 CD69.1 CD70.1 PC609.1 PJ600.2 RC19.1 RD17.1 RD21.1 RD22.1 RD81.2 RD82.2 UC1.5 UCPU1.AP1 UCPU1.AV1 UCPU1.BA14 UCPU1.BB1 UCPU1.BC14 UCPU1.BE14 UCPU1.BF1 UCPU1.BK1 UCPU1.BP1 UCPU1.BV1 UCPU1.CB1 UCPU1.CF1 UCPU1.CL1 UCPU1.CM3 UCPU1.CR1 UCPU1.CT3 UCPU1.CW1 UCPU1.CY3 UD1.A1 UD1.A8 UD1.B2 UD1.C1 UD1.C9 UD1.D2 UD1.D9 UD1.E9 UD1.F1 UD1.G7 UD1.H2 UD1.H9 UD1.K2 UD1.K8 UD1.N1 UD1.N9 UD1.R1 UD1.R9 UD2.A1 UD2.A8 UD2.B2 UD2.C1 UD2.C9 UD2.D2 UD2.D9 UD2.E9 UD2.F1 UD2.G7 UD2.H2 UD2.H9 UD2.K2 UD2.K8 UD2.N1 UD2.N9 UD2.R1 UD2.R9 UD3.A1 UD3.A8 UD3.B2 UD3.C1 UD3.C9 UD3.D2 UD3.D9 UD3.E9 UD3.F1 UD3.G7 UD3.H2 UD3.H9 UD3.K2 UD3.K8 UD3.N1 UD3.N9 UD3.R1 UD3.R9 UD4.A1 UD4.A8 UD4.B2 UD4.C1 UD4.C9 UD4.D2 UD4.D9 UD4.E9 UD4.F1 UD4.G7 UD4.H2 UD4.H9 UD4.K2 UD4.K8 UD4.N1 UD4.N9 UD4.R1 UD4.R9 UD5.A1 UD5.A8 UD5.B2 UD5.C1 UD5.C9 UD5.D2 UD5.D9 UD5.E9 UD5.F1 UD5.G7 UD5.H2 UD5.H9 UD5.K2 UD5.K8 UD5.N1 UD5.N9 UD5.R1 UD5.R9 UD6.A1 UD6.A8 UD6.B2 UD6.C1 UD6.C9 UD6.D2 UD6.D9 UD6.E9 UD6.F1 UD6.G7 UD6.H2 UD6.H9 UD6.K2 UD6.K8 UD6.N1 UD6.N9 UD6.R1 UD6.R9 UD7.A1 UD7.A8 UD7.B2 UD7.C1 UD7.C9 UD7.D2 UD7.D9 UD7.E9 UD7.F1 UD7.G7 UD7.H2 UD7.H9 UD7.K2 UD7.K8 UD7.N1 UD7.N9 UD7.R1 UD7.R9 UD8.A1 UD8.A8 UD8.B2 UD8.C1 UD8.C9 UD8.D2 UD8.D9 UD8.E9 UD8.F1 UD8.G7 UD8.H2 UD8.H9 UD8.K2 UD8.K8 UD8.N1 UD8.N9 UD8.R1 UD8.R9
+1.35VP: PC617.1 PJ600.1 PL601.1 PR605.2 PU600.5 PU600.19
+3.3V_M: C120.1 CH40.1 JSPI1.16 R161.2 R345.1 R346.2 RC47.1 UCPU1.A24 UCPU1.T25
+3.3V_SPI: CH7.1 CH8.1 JSPI1.15 RC47.2 RH47.1 RH48.1 U1.8 U2.8
+3.3V_SUS: C219.1 C253.1 CZ4.1 JUSH1.11 JUSH1.12 JUSH1.13 R307.2 RP14.5 RP14.6 RZ4.1 U61.5
+3.3VDX_SSD: C29.1 C30.1 C31.1 C32.1 C134.1 C249.1 JNGFF3.2 JNGFF3.4 JNGFF3.62 JNGFF3.64 JNGFF3.66 R191.2
+3V_PCH: C97.1 CH50.1 CH89.1 JAPS1.12 JAPS1.18 R2.1 R12.1 R291.2 RH12.1 RH100.2 RH109.2 RH110.1 RH111.1 RH129.1 RH136.2 RH146.1 RH175.1 RP5.5 RP5.6 RP5.7 RP5.8 RP7.7 RP7.8 RP8.2 RP9.5 RP9.6 RP9.7 RP9.8 RP23.5 RP23.6 RP23.7 RP23.8 U4.16 U5.5 U37.5 UCPU1.AL14 UCPU1.U18
+3V_PCH_DSW: C205.2 CH78.1 RH58.2 RH80.1 RH107.2 RH145.2 RH146.2 RP8.3 RP8.4 UCPU1.AA1 UCPU1.AB14
+3VALW: C100.1 C101.1 C110.1 C115.1 C116.1 C117.1 C131.1 C136.1 C197.1 C199.1 C214.1 C220.1 C255.1 JAPS1.16 JSNR1.2 PC80.1 PC514.1 PC900.1 PC901.1 PC902.1 PC905.1 PJ301.2 PR3.1 PR13.1 PR40.1 PR61.1 PR63.1 PR65.1 PR73.1 PR74.1 PR81.1 PR94.1 PR102.1 PR404.2 PR409.2 PR504.1 PR506.1 PR530.1 PR604.1 PR903.1 PR904.1 PR908.1 PR910.1 PU400.7 PU401.7 PU500.7 PU900.8 PU901.5 PU902.5 PU904.8 R206.1 R284.1 R335.1 R336.1 RH145.1 U6.4 U6.5 U24.1 U24.2 U25.6 U25.7 U26.1 U26.2 U26.6 U26.7 U27.1 U27.2 U27.6 U27.7 U29.1 U29.2 U29.6 U29.7 U30.6 U30.7 U33.1 U33.2 U34.1 U34.2 U46.4 U54.5
